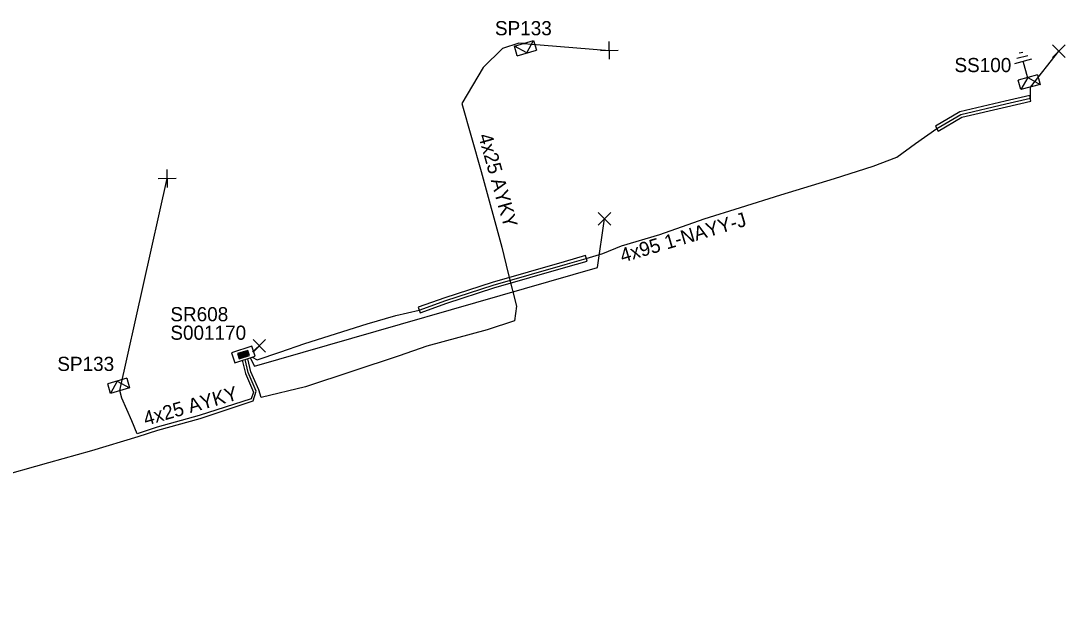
# Model space of a CAD drawing. Extents: x -762504 to -761250, y -1152974 to -1152253.
# Drawn here: x -761326.7 to -761253.4, y -1152324.6 to -1152282.8 of the extents above; entities that cross this region are included whole.
import ezdxf

# ---------------------------------------------------------------- set-up
doc = ezdxf.new("R2010")
doc.units = 0
for name, color, linetype in [('Vrstva 15', 7, 'Continuous'), ('Vrstva 20', 7, 'Continuous'), ('Vrstva 28', 7, 'Continuous'), ('Vrstva 29', 7, 'Continuous'), ('Vrstva 30', 7, 'Continuous'), ('Vrstva 31', 7, 'Continuous'), ('Vrstva 33', 7, 'Continuous'), ('Vrstva 34', 7, 'Continuous'), ('Vrstva 5', 7, 'Continuous'), ('Vrstva 59', 7, 'Continuous'), ('Vrstva 6', 7, 'Continuous')]:
    doc.layers.add(name, color=color, linetype=linetype)

msp = doc.modelspace()

# ---------------------------------------------------------------- linework, layer by layer
at = {"layer": 'Vrstva 15'}
for points in [[(-761256.907, -1152285.797), (-761255.7, -1152285.474)], [(-761256.755, -1152285.435), (-761255.994, -1152285.232)], [(-761256.594, -1152285.066), (-761256.465, -1152285.032)], [(-761256.465, -1152285.032), (-761256.342, -1152284.999)], [(-761255.98, -1152286.843), (-761256.304, -1152285.636)]]:
    msp.add_lwpolyline(points, dxfattribs=at)
at = {"layer": 'Vrstva 20'}
for points in [[(-761255.85, -1152288.06), (-761257.58, -1152288.45), (-761260.77, -1152289.2), (-761262.48, -1152290.21), (-761262.28, -1152290.55), (-761260.62, -1152289.58), (-761257.49, -1152288.84), (-761255.77, -1152288.45)], [(-761287.06, -1152299.3), (-761288.55, -1152299.74), (-761293.61, -1152301.19), (-761296.93, -1152302.27), (-761298.81, -1152302.93), (-761298.67, -1152303.31), (-761296.81, -1152302.65), (-761293.49, -1152301.57), (-761288.43, -1152300.12), (-761286.94, -1152299.68)]]:
    msp.add_lwpolyline(points, close=True, dxfattribs=at)
at = {"layer": 'Vrstva 28'}
for points in [[(-761310.489, -1152305.659), (-761311.916, -1152306.122)], [(-761310.785, -1152305.954), (-761311.493, -1152306.184)], [(-761310.815, -1152306.013), (-761311.433, -1152306.214)], [(-761310.728, -1152306.283), (-761310.815, -1152306.013)], [(-761310.668, -1152306.313), (-761310.785, -1152305.954)], [(-761310.258, -1152306.372), (-761310.489, -1152305.659)], [(-761311.916, -1152306.122), (-761311.684, -1152306.836)], [(-761311.684, -1152306.836), (-761310.258, -1152306.372)], [(-761311.493, -1152306.184), (-761311.376, -1152306.543)], [(-761311.433, -1152306.214), (-761311.345, -1152306.483)], [(-761311.376, -1152306.543), (-761310.668, -1152306.313)], [(-761310.846, -1152306.073), (-761311.374, -1152306.244)], [(-761311.374, -1152306.244), (-761311.315, -1152306.424)], [(-761311.345, -1152306.483), (-761310.728, -1152306.283)], [(-761311.315, -1152306.424), (-761310.787, -1152306.252)], [(-761310.876, -1152306.132), (-761311.314, -1152306.275)], [(-761311.314, -1152306.275), (-761311.285, -1152306.364)], [(-761311.285, -1152306.364), (-761310.847, -1152306.222)], [(-761310.901, -1152306.19), (-761311.26, -1152306.307)], [(-761310.847, -1152306.222), (-761310.876, -1152306.132)], [(-761310.787, -1152306.252), (-761310.846, -1152306.073)]]:
    msp.add_lwpolyline(points, dxfattribs=at)
at = {"layer": 'Vrstva 31'}
for points in [[(-761291.847, -1152285.265), (-761292.052, -1152284.596), (-761290.713, -1152284.187), (-761290.509, -1152284.856)], [(-761291.178, -1152285.061), (-761292.052, -1152284.596)], [(-761291.178, -1152285.061), (-761290.713, -1152284.187)], [(-761291.847, -1152285.265), (-761290.509, -1152284.856)], [(-761255.312, -1152286.602), (-761256.665, -1152286.964)], [(-761255.312, -1152286.602), (-761255.131, -1152287.278), (-761256.483, -1152287.64), (-761256.665, -1152286.964)], [(-761255.988, -1152286.783), (-761256.483, -1152287.64)], [(-761255.988, -1152286.783), (-761255.131, -1152287.278)], [(-761319.277, -1152307.913), (-761320.623, -1152308.299)], [(-761319.277, -1152307.913), (-761319.084, -1152308.586), (-761320.43, -1152308.972), (-761320.623, -1152308.299)], [(-761319.95, -1152308.106), (-761320.43, -1152308.972)], [(-761319.95, -1152308.106), (-761319.084, -1152308.586)]]:
    msp.add_lwpolyline(points, dxfattribs=at)
at = {"layer": 'Vrstva 34'}
for points in [[(-761285.369, -1152285.505), (-761285.391, -1152284.255)], [(-761254.252, -1152284.488), (-761253.368, -1152285.371)], [(-761254.252, -1152285.371), (-761253.368, -1152284.488)], [(-761286.005, -1152284.891), (-761284.755, -1152284.869)], [(-761316.429, -1152294.505), (-761316.451, -1152293.255)], [(-761317.065, -1152293.891), (-761315.815, -1152293.869)], [(-761286.162, -1152296.268), (-761285.278, -1152297.152)], [(-761286.162, -1152297.152), (-761285.278, -1152296.268)], [(-761310.412, -1152305.198), (-761309.528, -1152306.082)], [(-761310.412, -1152306.082), (-761309.528, -1152305.198)]]:
    msp.add_lwpolyline(points, dxfattribs=at)
at = {"layer": 'Vrstva 5'}
for points in [[(-761291.38, -1152284.39), (-761291.75, -1152284.37), (-761292.9, -1152284.74), (-761294.24, -1152286.09), (-761295.74, -1152288.61), (-761294.39, -1152293.4), (-761292.94, -1152298.7), (-761292.49, -1152300.56), (-761291.91, -1152302.86), (-761292.04, -1152303.87), (-761293.96, -1152304.5), (-761298.2, -1152305.67), (-761300.15, -1152306.34), (-761306.73, -1152308.52), (-761309.83, -1152309.27), (-761310.01, -1152308.73), (-761310.56, -1152307.46), (-761310.78, -1152306.54)], [(-761310.47, -1152306.43), (-761310.12, -1152306.61), (-761308.54, -1152306.08), (-761306.77, -1152305.47), (-761302.39, -1152304.08), (-761300.39, -1152303.51), (-761298.74, -1152303.12), (-761296.87, -1152302.46), (-761293.55, -1152301.38), (-761288.49, -1152299.93), (-761287, -1152299.49), (-761285.83, -1152299.14), (-761284.53, -1152298.61), (-761281.84, -1152297.81), (-761278.73, -1152296.72), (-761276.18, -1152295.93), (-761273.33, -1152295.04), (-761269.56, -1152293.88), (-761266.84, -1152293.02), (-761265.18, -1152292.38), (-761263.87, -1152291.43), (-761262.38, -1152290.38), (-761260.69, -1152289.39), (-761257.53, -1152288.64), (-761255.81, -1152288.25), (-761255.81, -1152287.46)], [(-761359.39, -1152321.52), (-761359.25, -1152321.9), (-761358.48, -1152324.57), (-761358.31, -1152324.62), (-761356.69, -1152324.09), (-761354.04, -1152323.04), (-761351.62, -1152322.3), (-761346.5, -1152320.46), (-761342.27, -1152319.37), (-761337.49, -1152317.85), (-761332.14, -1152316.05), (-761328.6, -1152314.9), (-761324.75, -1152313.83), (-761321.73, -1152312.99), (-761318.49, -1152312), (-761317.09, -1152311.55), (-761314.13, -1152310.74), (-761310.4, -1152309.51), (-761310.19, -1152308.81), (-761310.75, -1152307.52), (-761310.97, -1152306.6)], [(-761311.17, -1152306.65), (-761310.94, -1152307.58), (-761310.37, -1152308.89), (-761310.54, -1152309.35), (-761314.19, -1152310.54), (-761317.15, -1152311.35), (-761318.56, -1152311.82), (-761318.93, -1152310.9), (-761319.63, -1152309.31), (-761319.76, -1152308.78)]]:
    msp.add_lwpolyline(points, dxfattribs=at)
at = {"layer": 'Vrstva 59'}
for points in [[(-761291.38, -1152284.39), (-761285.38, -1152284.88)], [(-761255.81, -1152287.46), (-761253.81, -1152284.93)], [(-761319.76, -1152308.78), (-761316.44, -1152293.88)], [(-761310.62, -1152306.47), (-761310.31, -1152307.07), (-761286.21, -1152300.14), (-761285.72, -1152296.71)], [(-761310.44, -1152306.05), (-761309.97, -1152305.64)]]:
    msp.add_lwpolyline(points, dxfattribs=at)

# ---------------------------------------------------------------- texts
at = {"layer": 'Vrstva 29'}
msp.add_text('S001170', height=0.9943, dxfattribs=at).set_placement((-761316.22, -1152305.21))
at = {"layer": 'Vrstva 30'}
msp.add_text('SR608', height=0.9943, dxfattribs=at).set_placement((-761316.22, -1152303.91))
at = {"layer": 'Vrstva 33'}
for s, p in [('SP133', (-761293.42, -1152283.82)), ('SS100', (-761261.14, -1152286.41)), ('SP133', (-761324.16, -1152307.4))]:
    msp.add_text(s, height=0.9943, dxfattribs=at).set_placement(p)
at = {"layer": 'Vrstva 6'}
for s, height, rotation, p in [('4x25 AYKY', 0.9943, 285.69967, (-761294.6, -1152290.87)), ('4x95 1-NAYY-J', 0.99429, 16.56236, (-761284.46, -1152299.8)), ('4x25 AYKY', 0.9943, 15.78289, (-761317.95, -1152311.25))]:
    msp.add_text(s, height=height, rotation=rotation, dxfattribs=at).set_placement(p)

doc.saveas('drawing.dxf')
